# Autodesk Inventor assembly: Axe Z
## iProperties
Author: Philippe
Shininess: 41.0
Angle Display Precision: 2
Document Length Units: 11269
Document Angle Units: 11283
Document Time Units: 11279
Document Mass Units: 11290
Document Length Units Precision: 3
Document Angle Units Precision: 2
Compacted: False
PropertySet Name: _Private Model Information
Created: 2001-12
Part Number: Axe Z
Document SubType Name: Assemblage
Designer: Philippe
Control State: 0
Master: False
Checked Out: False
PropertySet Name: Design Tracking Control
Density: 0.0
Volumn: 0.0
Area: 0.0
PropertySet Name: Model Information
